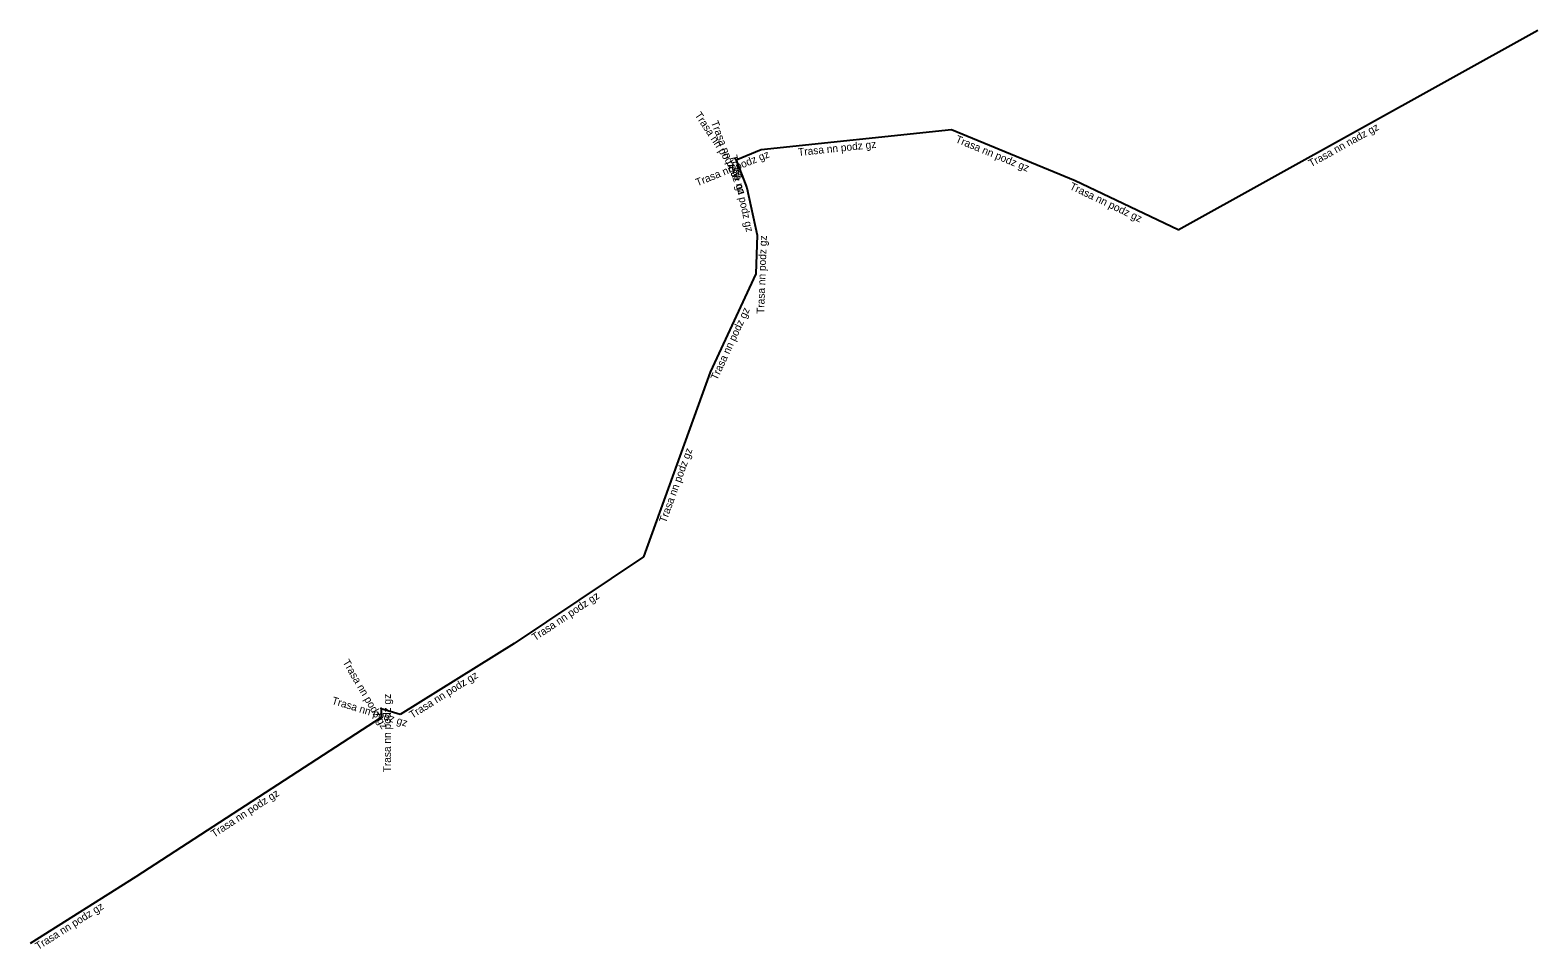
# Model space of a CAD drawing. Extents: x -597535 to -597331, y -1061212 to -1060957.
# Drawn here: x -597439 to -597339.8, y -1061101.3 to -1061040.9 of the extents above; entities that cross this region are included whole.
import ezdxf

# ---------------------------------------------------------------- set-up
doc = ezdxf.new("R2010")
doc.units = 0
doc.layers.add('Popiskový text - Ostatní atributy Trasy', color=7, linetype='Continuous')
doc.layers.add('Spojnice NN', color=7, linetype='Continuous')

msp = doc.modelspace()

# ---------------------------------------------------------------- linework, layer by layer
at = {"layer": 'Spojnice NN'}
for points in [[(-597363.5, -1061053.98), (-597339.84, -1061040.85)], [(-597378.42, -1061047.41), (-597390.94, -1061048.73)], [(-597370.28, -1061050.76), (-597378.42, -1061047.41)], [(-597392.593, -1061049.396), (-597392.694, -1061049.243)], [(-597390.94, -1061048.73), (-597392.593, -1061049.396)], [(-597392.593, -1061049.396), (-597391.89, -1061051.22)], [(-597391.89, -1061051.22), (-597391.21, -1061054.34)], [(-597363.5, -1061053.98), (-597370.28, -1061050.76)], [(-597391.21, -1061054.34), (-597391.3, -1061056.87)], [(-597391.3, -1061056.87), (-597394.29, -1061063.34)], [(-597394.29, -1061063.34), (-597398.69, -1061075.48)], [(-597398.69, -1061075.48), (-597407.2, -1061081.18)], [(-597407.2, -1061081.18), (-597414.68, -1061085.86)], [(-597415.95, -1061086.06), (-597432.09, -1061096.53)], [(-597415.95, -1061085.47), (-597415.988, -1061085.405)], [(-597415.95, -1061085.47), (-597415.95, -1061086.06)], [(-597414.68, -1061085.86), (-597415.95, -1061085.47)], [(-597432.09, -1061096.53), (-597439.033, -1061100.919)]]:
    msp.add_lwpolyline(points, dxfattribs=at)

# ---------------------------------------------------------------- texts
at = {"layer": 'Popiskový text - Ostatní atributy Trasy'}
for s, rotation, p in [('Trasa nn podz gz', 303.43003, (-597395.331, -1061046.428)), ('Trasa nn podz gz', 291.07749, (-597394.249, -1061046.909)), ('Trasa nn nadz gz', 29.02787, (-597354.759, -1061049.873)), ('Trasa nn podz gz', 6.01853, (-597388.484, -1061049.125)), ('Trasa nn podz gz', 337.63049, (-597378.198, -1061048.204)), ('Trasa nn podz gz', 21.94469, (-597395.135, -1061051.121)), ('Trasa nn podz gz', 282.29527, (-597393.014, -1061049.114)), ('Trasa nn podz gz', 334.59573, (-597370.686, -1061051.286)), ('Trasa nn podz gz', 87.96267, (-597390.744, -1061059.519)), ('Trasa nn podz gz', 65.19679, (-597393.838, -1061063.912)), ('Trasa nn podz gz', 70.07755, (-597397.206, -1061073.292)), ('Trasa nn podz gz', 33.81418, (-597405.818, -1061081.037)), ('Trasa nn podz gz', 300.31122, (-597418.495, -1061082.404)), ('Trasa nn podz gz', 32.03292, (-597413.896, -1061086.136)), ('Trasa nn podz gz', 342.92898, (-597419.228, -1061085.143)), ('Trasa nn podz gz', 90, (-597415.3, -1061089.659)), ('Trasa nn podz gz', 32.97143, (-597426.933, -1061093.96)), ('Trasa nn podz gz', 32.29892, (-597438.506, -1061101.355))]:
    msp.add_text(s, height=0.5, rotation=rotation, dxfattribs=at).set_placement(p)

doc.saveas('drawing.dxf')
